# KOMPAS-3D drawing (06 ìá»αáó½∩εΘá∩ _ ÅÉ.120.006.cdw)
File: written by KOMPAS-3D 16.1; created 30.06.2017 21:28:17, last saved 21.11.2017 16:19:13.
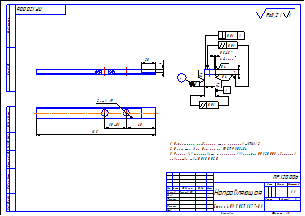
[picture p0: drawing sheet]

Sheet 1: A3, landscape

Title block, sheet 1: name: Направляющая; designation: ПР.120.006; material: Сталь 40Х ГОСТ 1577-81; scale: 1:1; sheets: 1; sheet format: A3; stored path: D:\VSE\Эрга\Оснастка\Гибка лепестков\Прохвост\Направляющая _ К17.479.006.cdw; drawn by: Сигачев СИ

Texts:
  Sergey
  Неуказанные предельные откл. размеров  (IT14)/2.
  Покрытие: Хим. Окс. прм по ГОСТ 9.303-84.
  Размер "г" согласовать с размером "в" корпуса ПР.120.003, обеспечив
  равенство г=в-(0,015...0,025).
  Ra3,2
  Ra3,2 ( )
  CONTINUOUS_RGB_0_255_0_THICK_0.18
  CONTINUOUS_RGB_0_0_255_THICK_0.18
Dimensions and other numbers on the sheet: 4; 20; 2 отв.; 9; 30±0,1; 40; 165; 7; 0,4; 0,5; 4 фаски; 15; 0,01; 1:1; 1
